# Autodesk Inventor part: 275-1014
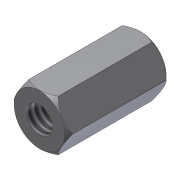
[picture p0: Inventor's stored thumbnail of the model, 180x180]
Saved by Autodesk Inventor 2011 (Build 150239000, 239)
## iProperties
Company: Autodesk Inc.
Created: 2005-07
Part Number: 275-1014
Document SubType Name: Modeling
Designer: Autodesk Inc.
Density: 1 g/cm^3
Catalog Web Link: http://www.vexrobotics.com/products/accessories/structure/standoffs-8-32.html
Description: A standoff is used in mechanics and electronics to separate two parts from one another. All VEX Standoffs have 8-32 threads.
Vendor: Innovation First, Inc.
Author: Autodesk Inc.
Title: Threaded Beam 0.5 inch
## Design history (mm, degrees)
sketch "Sketch1"
  geometry: L1 (1.955, -3.175)-(-1.711, -3.175); L2 (-1.711, -3.175)-(-3.544, 0); L3 (-3.544, 0)-(-1.711, 3.175); L4 (-1.711, 3.175)-(1.955, 3.175); L5 (1.955, 3.175)-(3.788, 0); L6 (3.788, 0)-(1.955, -3.175); 1 further point
  constraints: 12 end point, 1 horizontal, 11 other
  dimensions: "d0" = 6.35 distance between parallel lines of L1 L4
extrude "Extrusion1" new body sketch "Sketch1" distance "d1" = 12.7; taper "d2" = 0 deg
workplane "Work Plane1"
sketch "Sketch3"
  geometry: L1 (-1.325, 0)-(4.974, 0); L2 (5.482, -0.508)-(5.482, -12.192); L3 (4.974, -12.7)-(-1.325, -12.7); L4 (-1.833, -12.192)-(-1.833, -0.508); L5 (-1.833, -0.508)-(-1.325, 0); L6 (4.974, 0)-(5.482, -0.508); L7 (-1.325, -12.7)-(-1.833, -12.192); L8 (5.482, -12.192)-(4.974, -12.7); L9 (-1.833, 0)-(-1.833, -12.7) reference; L10 (3.666, 0)-(5.499, 0) reference; L11 (1.825, 0)-(1.825, -12.7); 4 further points
  constraints: 18 end point, 8 point on line, 2 midpoint, 2 parallel, 1 horizontal, 1 perpendicular
  dimensions: "d5" = 0.508 distance of L4.end point (-1.833, 0); "d6" = 0.508 distance of L1.start point (-1.833, 0) (= d5); "d7" = 0.508 distance of L1.end point (5.482, 0) (= d5); "d8" = 0.508 distance of L2.start point (5.482, 0) (= d7); "d9" = 0.508 distance of L3.end point (-1.833, -12.7) (= d5); "d10" = 0.508 distance of L4.start point (-1.833, -12.7) (= d9); "d11" = 0.508 distance of L2.end point (5.482, -12.7) (= d5); "d12" = 0.508 distance of L3.start point (5.482, -12.7) (= d11); "d13" = 7.3152 distance between parallel lines of L2 L4; "d14" = 0 distance between parallel lines of L9 L4; "d15" = 12.7 distance between parallel lines of L1 L3; "d16" = 0 distance between parallel lines of L1 L10
revolve "Revolution1" sketch "Sketch3" stored, may be unused: angle "d17" = 90 deg
sketch "Sketch4"
  geometry: C1 r 3.15 at (0, 0) reference; 1 further point
  constraints: 1 coincident
hole "Hole1" sketch "Sketch4" at (0, 0) diameter "d18" = 3.302; stored, may be unused: countersink angle "d22" = 82 deg, drill point angle "d24" = 118 deg; dims "d19" = 12.7, "d20" = 9.525, "d21" = 6.35, "d23" = 12.7
body "Solid1"
other parameters: "d4" = -3.175
